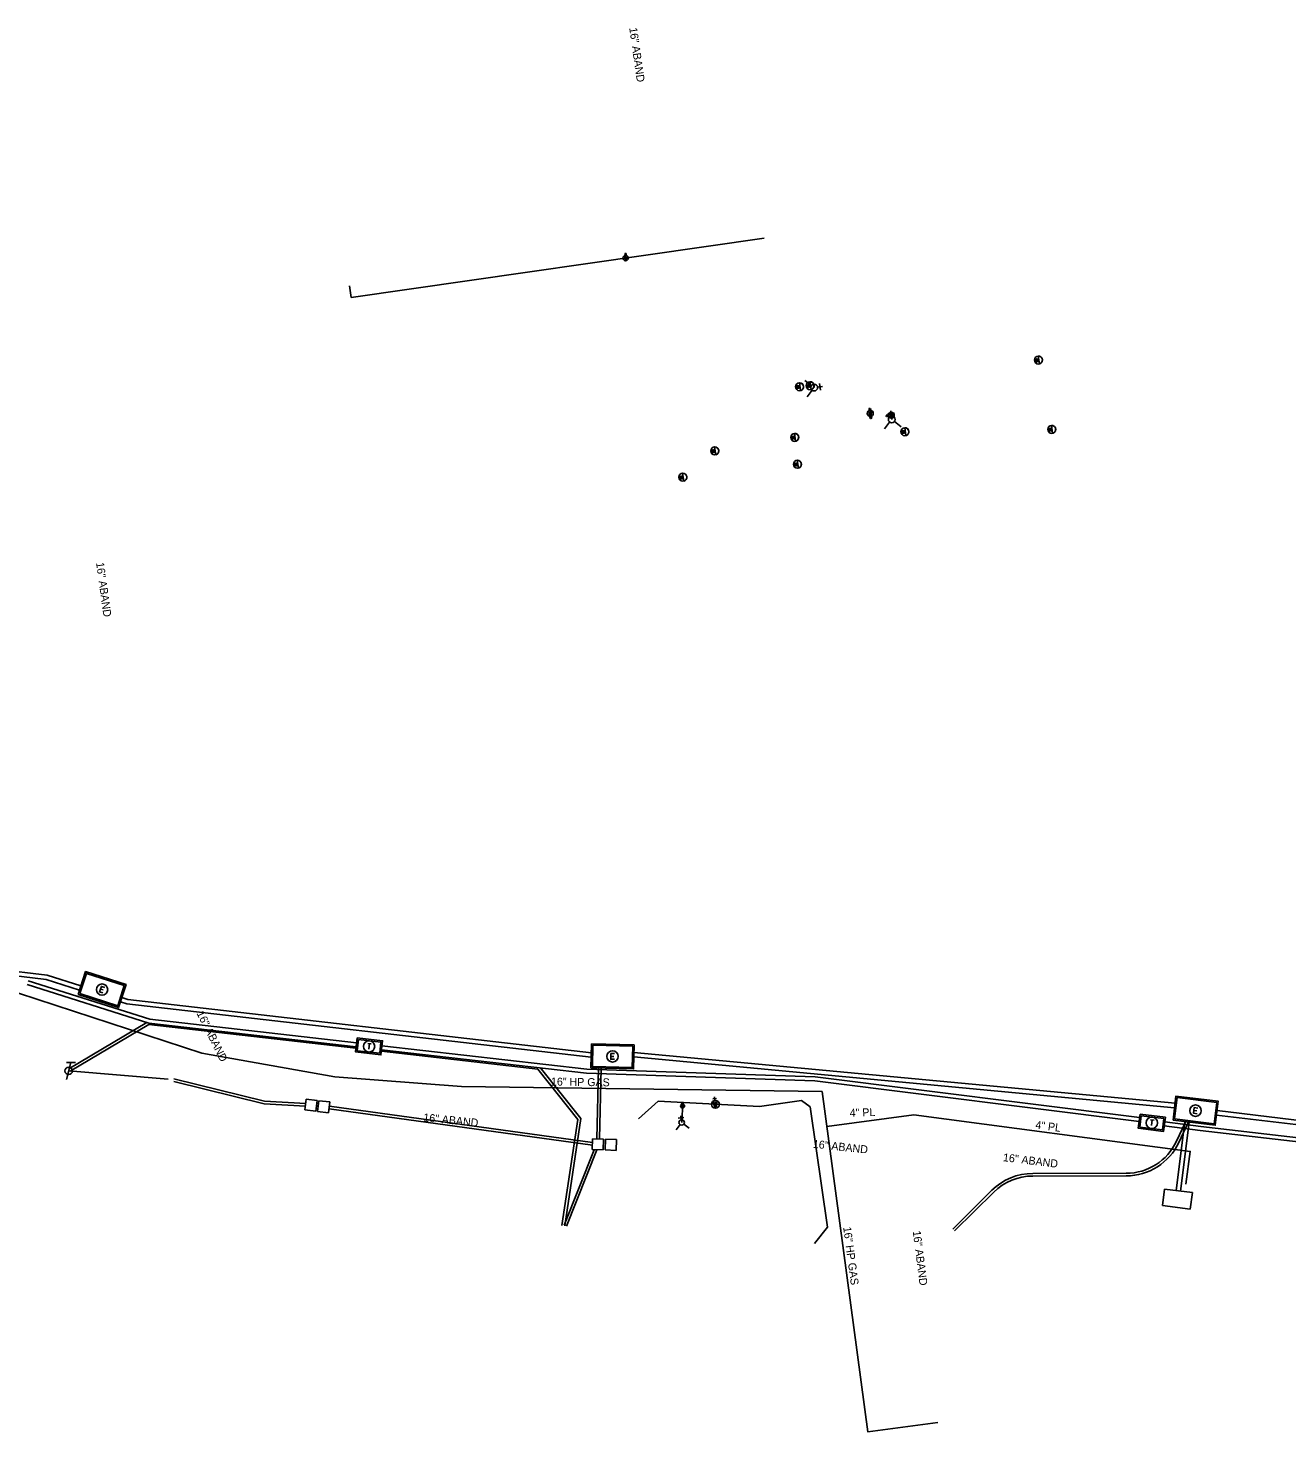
# Model space of a CAD drawing. Extents: x 1825330 to 1832613, y 710925 to 712586.
# Drawn here: x 1827870.9 to 1828314.3, y 711497 to 711991.4 of the extents above; entities that cross this region are included whole.
import ezdxf

# ---------------------------------------------------------------- set-up
doc = ezdxf.new("R2010")
doc.units = 0
for name, color, linetype in [('COC_BLD', 7, 'Continuous'), ('COC_UELC_GUY', 7, 'Continuous'), ('COC_USAN_MH', 7, 'Continuous'), ('COC_USAN_MH_TEXT', 7, 'Continuous'), ('COC_UWAT_HYD', 7, 'Continuous'), ('P-TEXT', 7, 'Continuous'), ('STDSHT', 7, 'Continuous'), ('ZM-BORDERS', 7, 'Continuous')]:
    doc.layers.add(name, color=color, linetype=linetype)

msp = doc.modelspace()

# ---------------------------------------------------------------- linework, layer by layer
msp.add_lwpolyline([(1828262.52, 711608.89), (1828271.45, 711607.78), (1828270.83, 711602.81), (1828261.9, 711603.93)], close=True)
at = {"layer": 'COC_UELC_GUY'}
for p, q in [((1827984.65, 711896.54), (1828130.11, 711917.41)), ((1827984.06, 711900.61), (1827984.65, 711896.54)), ((1828175.08, 711853.55), (1828174.73, 711856.54)), ((1828085.9, 711607.25), (1828092.77, 711613.44)), ((1828092.77, 711613.44), (1828128.48, 711611.57)), ((1828101.1, 711605.99), (1828101.46, 711612.98)), ((1828128.48, 711611.57), (1828143.32, 711613.73)), ((1828146.36, 711611.46), (1828143.32, 711613.73))]:
    msp.add_line(p, q, dxfattribs=at)
msp.add_lwpolyline([(1828147.91, 711563.32), (1828152.51, 711569.04), (1828146.36, 711611.46)], dxfattribs=at)
at = {"layer": 'COC_USAN_MH'}
msp.add_line((1828023.5, 711618.65), (1828150.6, 711616.84), dxfattribs=at)
for points in [[(1827861.07, 711653.59), (1827932.11, 711630.33), (1827978.94, 711622.09), (1828023.5, 711618.65)], [(1828150.6, 711616.84), (1828166.68, 711496.98), (1828191.27, 711500.35)], [(1828152.25, 711604.52), (1828182.89, 711608.64), (1828280.19, 711595.75), (1828278.63, 711584.24)]]:
    msp.add_lwpolyline(points, dxfattribs=at)
at = {"layer": 'COC_USAN_MH_TEXT'}
for p, q in [((1827870.9, 711655.89), (1827913.78, 711642.33)), ((1827870.6, 711654.5), (1827913.48, 711640.94)), ((1827885.24, 711624.88), (1827912.71, 711641.18)), ((1827913.78, 711642.33), (1827986.6, 711633.99)), ((1827885.75, 711624.02), (1827913.43, 711640.44)), ((1827913.43, 711640.44), (1827986.38, 711632.08)), ((1827913.48, 711640.94), (1827986.44, 711632.58)), ((1827991.78, 711633.65), (1827990.54, 711633.8)), ((1827991.12, 711633.73), (1827990.87, 711631.74)), ((1827995.38, 711631.55), (1828067.61, 711623.28)), ((1827995.54, 711632.96), (1828067.71, 711624.69)), ((1827995.32, 711631.06), (1828050.46, 711624.74)), ((1828050.46, 711624.74), (1828064.54, 711607.02)), ((1828051.25, 711625.36), (1828065.58, 711607.32)), ((1828067.61, 711623.28), (1828148, 711620.63)), ((1828067.71, 711624.69), (1828148.11, 711622.05)), ((1828148.11, 711622.05), (1828262.38, 711607.77)), ((1828148, 711620.63), (1828262.2, 711606.36)), ((1828058.92, 711569.63), (1828064.54, 711607.02)), ((1828059.9, 711569.52), (1828065.58, 711607.32)), ((1828267.46, 711606.77), (1828266.22, 711606.92)), ((1828266.8, 711606.86), (1828266.55, 711604.87)), ((1828271.07, 711604.75), (1828283.72, 711603.17)), ((1828271.25, 711606.16), (1828283.9, 711604.57)), ((1828283.73, 711603.17), (1828515.03, 711576.14)), ((1828283.9, 711604.57), (1828515.2, 711577.54))]:
    msp.add_line(p, q, dxfattribs=at)
for points in [[(1827986.8, 711635.76), (1827995.75, 711634.74), (1827995.18, 711629.77), (1827986.23, 711630.8)], [(1827987.24, 711635.21), (1827995.19, 711634.3), (1827994.74, 711630.33), (1827986.79, 711631.24)], [(1828262.95, 711608.33), (1828270.89, 711607.34), (1828270.39, 711603.37), (1828262.46, 711604.36)]]:
    msp.add_lwpolyline(points, close=True, dxfattribs=at)
for centre in [(1827990.99, 711632.77), (1828266.67, 711605.85)]:
    msp.add_circle(centre, 2, dxfattribs=at)
at = {"layer": 'COC_UWAT_HYD'}
for p, q in [((1827706.52, 711678.86), (1827877.6, 711657.83)), ((1827706.54, 711677.26), (1827877.26, 711656.28)), ((1827877.26, 711656.28), (1827889.03, 711652.56)), ((1827877.6, 711657.83), (1827889.5, 711654.07)), ((1827896.41, 711652.96), (1827897.36, 711652.65)), ((1827903.44, 711648.41), (1827905.73, 711647.69)), ((1827903.92, 711649.92), (1827906.06, 711649.24)), ((1827905.73, 711647.69), (1828069.24, 711628.94)), ((1827906.06, 711649.24), (1828069.28, 711630.53)), ((1828076.17, 711629.25), (1828077.17, 711629.23)), ((1828084.2, 711629.05), (1828274.71, 711611.17)), ((1828084.29, 711630.63), (1828274.88, 711612.75)), ((1827885.2, 711624.12), (1827920.28, 711621.24)), ((1828071.78, 711625.09), (1828071.19, 711600.18)), ((1828072.7, 711625.07), (1828072.11, 711600.16)), ((1827968.39, 711610.38), (1827968.85, 711614.18)), ((1827968.85, 711614.18), (1827972.66, 711613.72)), ((1827972.66, 711613.72), (1827972.2, 711609.92)), ((1827972.88, 711609.83), (1827973.34, 711613.64)), ((1827973.34, 711613.64), (1827977.14, 711613.18)), ((1827977.14, 711613.18), (1827976.68, 711609.37)), ((1827977.02, 711611.73), (1828069.65, 711598.91)), ((1827972.2, 711609.92), (1827968.39, 711610.38)), ((1827976.68, 711609.37), (1827972.88, 711609.83)), ((1827976.91, 711610.8), (1828069.7, 711597.95)), ((1828281.49, 711610.21), (1828282.48, 711610.08)), ((1828289.47, 711608.57), (1828500.81, 711583.36)), ((1828289.66, 711610.14), (1828501, 711584.94)), ((1828278.32, 711606.31), (1828275.28, 711582)), ((1828275.35, 711599.33), (1828278.6, 711606.27)), ((1828276.18, 711598.94), (1828279.56, 711606.15)), ((1828279.8, 711606.12), (1828276.76, 711581.81)), ((1828069.61, 711596.4), (1828069.73, 711600.23)), ((1828069.73, 711600.23), (1828073.56, 711600.11)), ((1828073.56, 711600.11), (1828073.44, 711596.28)), ((1828074.14, 711596.27), (1828074.27, 711600.1)), ((1828074.27, 711600.1), (1828078.1, 711599.97)), ((1828078.1, 711599.97), (1828077.97, 711596.14)), ((1828070.23, 711596.38), (1828059.69, 711569.76)), ((1828071.21, 711596.35), (1828060.55, 711569.42)), ((1828073.44, 711596.28), (1828069.61, 711596.4)), ((1828077.97, 711596.14), (1828074.14, 711596.27)), ((1828224.75, 711588.03), (1828257.67, 711588.07)), ((1828224.75, 711587.11), (1828257.67, 711587.15)), ((1828196.58, 711568.42), (1828210.36, 711582.1)), ((1828270.43, 711576.74), (1828271.18, 711582.53)), ((1828271.18, 711582.53), (1828280.98, 711581.26)), ((1828197.23, 711567.77), (1828211.01, 711581.44)), ((1828280.98, 711581.26), (1828280.23, 711575.47)), ((1828280.23, 711575.47), (1828270.43, 711576.74))]:
    msp.add_line(p, q, dxfattribs=at)
for points in [[(1827888.52, 711651.02), (1827891.13, 711659.11), (1827905.41, 711654.52), (1827902.8, 711646.42)], [(1827889.15, 711651.34), (1827891.45, 711658.48), (1827904.78, 711654.19), (1827902.48, 711647.05)], [(1828069.15, 711625.16), (1828069.36, 711633.65), (1828084.35, 711633.3), (1828084.15, 711624.8)], [(1828069.84, 711633.14), (1828083.84, 711632.81), (1828083.66, 711625.31), (1828069.66, 711625.64)], [(1828274.14, 711606.83), (1828275.19, 711615.27), (1828290.08, 711613.41), (1828289.02, 711604.97)], [(1828275.63, 711614.71), (1828289.52, 711612.97), (1828288.59, 711605.53), (1828274.7, 711607.27)]]:
    msp.add_lwpolyline(points, close=True, dxfattribs=at)
for points in [[(1827897.91, 711653.53), (1827896.72, 711653.91), (1827896.1, 711652), (1827897.29, 711651.62)], [(1828077.44, 711630.22), (1828076.19, 711630.25), (1828076.14, 711628.25), (1828077.39, 711628.22)], [(1827922.26, 711621.35), (1827954.21, 711613.47), (1827968.74, 711612.69)], [(1827922.24, 711620.43), (1827954, 711612.56), (1827968.62, 711611.73)], [(1828282.86, 711611.04), (1828281.61, 711611.2), (1828281.37, 711609.21), (1828282.61, 711609.06)]]:
    msp.add_lwpolyline(points, dxfattribs=at)
for centre in [(1827896.96, 711652.77), (1828076.75, 711629.23), (1828282.07, 711610.12)]:
    msp.add_circle(centre, 2, dxfattribs=at)
for centre, radius, start, end in [((1828257.65, 711607.61), 19.54, 270.0553, 334.9333), ((1828257.65, 711607.61), 20.46, 270.0553, 334.9333), ((1828224.77, 711567.57), 20.46, 90.0553, 134.7815), ((1828224.77, 711567.57), 19.54, 90.0553, 134.7815)]:
    msp.add_arc(centre, radius, start, end, dxfattribs=at)
at = {"layer": 'P-TEXT'}
for p, q in [((1828081.79, 711911.8), (1828080.92, 711911.8)), ((1828081.35, 711911.37), (1828081.35, 711912.23)), ((1828227.09, 711873.12), (1828226.69, 711875.87)), ((1828142.94, 711863.71), (1828142.54, 711866.47)), ((1828146.82, 711865.51), (1828144.47, 711867.28)), ((1828147.06, 711863.84), (1828145.3, 711861.48)), ((1828146.65, 711864.08), (1828146.25, 711866.84)), ((1828148.97, 711864.97), (1828150.67, 711865.21)), ((1828149.99, 711863.9), (1828149.65, 711866.28)), ((1828167.79, 711857.29), (1828166.84, 711857.15)), ((1828167.38, 711856.75), (1828167.25, 711857.69)), ((1828167.32, 711854.24), (1828168.08, 711854.33)), ((1828167.66, 711854.67), (1828167.75, 711853.9)), ((1828173.87, 711854.89), (1828172.93, 711854.74)), ((1828173.32, 711855.29), (1828173.47, 711854.34)), ((1828176.02, 711855.74), (1828173.64, 711855.45)), ((1828174.93, 711854.74), (1828174.72, 711856.45)), ((1828174.34, 711852.6), (1828172.53, 711850.29)), ((1828176.02, 711852.81), (1828178.34, 711851)), ((1828180.03, 711847.87), (1828179.64, 711850.63)), ((1828231.75, 711848.71), (1828231.36, 711851.46)), ((1828113.08, 711841.11), (1828112.68, 711843.87)), ((1828141.24, 711845.89), (1828140.84, 711848.65)), ((1828142.19, 711836.43), (1828141.79, 711839.19)), ((1828101.83, 711831.87), (1828101.43, 711834.62)), ((1828101.57, 711612.86), (1828100.93, 711612.76)), ((1828101.3, 711612.49), (1828101.2, 711613.13)), ((1828113.35, 711614.45), (1828112.09, 711614.29)), ((1828112.8, 711613.74), (1828112.64, 711615)), ((1828101.81, 711607.76), (1828099.91, 711607.49)), ((1828100.96, 711606.94), (1828100.76, 711608.31)), ((1828100.53, 711605.22), (1828099.12, 711603.34)), ((1828101.87, 711605.42), (1828103.75, 711604.01))]:
    msp.add_line(p, q, dxfattribs=at)
for points in [[(1828080.92, 711910.96), (1828081.14, 711909.79), (1828081.35, 711910.96), (1828081.57, 711909.79), (1828081.79, 711910.96)], [(1828225.71, 711874.89), (1828226.07, 711873.81), (1828226.12, 711874.95), (1828226.48, 711873.87), (1828226.53, 711875.01)], [(1828141.56, 711865.49), (1828141.92, 711864.41), (1828141.97, 711865.55), (1828142.33, 711864.47), (1828142.38, 711865.61)], [(1828145.27, 711865.86), (1828145.64, 711864.78), (1828145.68, 711865.92), (1828146.05, 711864.84), (1828146.09, 711865.98)], [(1828166.97, 711856.24), (1828167.4, 711854.99), (1828167.45, 711856.31), (1828167.87, 711855.06), (1828167.92, 711856.38)], [(1828174.38, 711854.48), (1828175.62, 711854.91), (1828174.31, 711854.95), (1828175.55, 711855.39), (1828174.24, 711855.43)], [(1828178.65, 711849.64), (1828179.02, 711848.56), (1828179.06, 711849.7), (1828179.43, 711848.62), (1828179.47, 711849.76)], [(1828230.37, 711850.48), (1828230.74, 711849.4), (1828230.78, 711850.54), (1828231.15, 711849.46), (1828231.19, 711850.6)], [(1828139.86, 711847.67), (1828140.22, 711846.59), (1828140.27, 711847.73), (1828140.63, 711846.65), (1828140.68, 711847.79)], [(1828111.69, 711842.89), (1828112.06, 711841.81), (1828112.1, 711842.95), (1828112.47, 711841.87), (1828112.51, 711843)], [(1828140.81, 711838.21), (1828141.17, 711837.13), (1828141.22, 711838.27), (1828141.58, 711837.19), (1828141.63, 711838.33)], [(1828100.45, 711833.64), (1828100.81, 711832.56), (1828100.86, 711833.7), (1828101.22, 711832.62), (1828101.27, 711833.76)], [(1828101.02, 711612.14), (1828101.31, 711611.29), (1828101.34, 711612.18), (1828101.63, 711611.34), (1828101.66, 711612.23)], [(1828112.24, 711613.07), (1828112.77, 711611.4), (1828112.87, 711613.15), (1828113.4, 711611.48), (1828113.51, 711613.23)]]:
    msp.add_lwpolyline(points, dxfattribs=at)
for centre, radius in [((1828081.35, 711910.42), 0.952), ((1828226.75, 711874.47), 1.4), ((1828142.6, 711865.07), 1.4), ((1828146.31, 711865.44), 1.4), ((1828147.78, 711864.8), 1.2), ((1828167.53, 711855.71), 1.05), ((1828167.7, 711854.28), 0.386), ((1828174.91, 711855.05), 1.05), ((1828175.08, 711853.55), 1.2), ((1828179.7, 711849.23), 1.4), ((1828231.42, 711850.06), 1.4), ((1828112.74, 711842.47), 1.4), ((1828140.9, 711847.25), 1.4), ((1828141.85, 711837.79), 1.4), ((1828101.49, 711833.23), 1.4), ((1828101.4, 711611.78), 0.717), ((1828112.97, 711612.35), 1.4), ((1828101.1, 711605.99), 0.96)]:
    msp.add_circle(centre, radius, dxfattribs=at)
for centre in [(1828226.75, 711874.47), (1828226.75, 711874.47), (1828142.6, 711865.07), (1828142.6, 711865.07), (1828146.31, 711865.44), (1828146.31, 711865.44), (1828179.7, 711849.23), (1828179.7, 711849.23), (1828231.42, 711850.06), (1828231.42, 711850.06), (1828112.74, 711842.47), (1828112.74, 711842.47), (1828140.9, 711847.25), (1828140.9, 711847.25), (1828141.85, 711837.79), (1828141.85, 711837.79), (1828101.49, 711833.23), (1828101.49, 711833.23)]:
    msp.add_arc(centre, 1.4, 283.9445, 92.4652, dxfattribs=at)
at = {"layer": 'STDSHT'}
for p, q in [((1827886, 711627.12), (1827884.39, 711621.12)), ((1827887.6, 711627.12), (1827884.4, 711627.12))]:
    msp.add_line(p, q, dxfattribs=at)
msp.add_circle((1827885.2, 711624.12), 1.3, dxfattribs=at)
at = {"layer": 'ZM-BORDERS'}
msp.add_line((1828147.64, 711865.79), (1828147.78, 711864.8), dxfattribs=at)

# ---------------------------------------------------------------- texts
at = {"layer": 'COC_BLD'}
for s, rotation, p in [('16" ABAND', 278.1514, (1828082.61, 711991.43)), ('16" ABAND', 277.8948, (1827894.85, 711803.09)), ('16" ABAND', 296.3017, (1827930.16, 711644.45)), ('16" HP GAS', 359.1807, (1828055.05, 711618.98)), ('16" ABAND', 354.0561, (1828010, 711606.43)), ('4" PL', 1.9522, (1828160.31, 711607.94)), ('4" PL', 352.467, (1828225.53, 711603.83)), ('16" ABAND', 353.8253, (1828147.2, 711597.09)), ('16" ABAND', 352.9939, (1828214.15, 711592.36)), ('16" HP GAS', 277.6433, (1828157.96, 711569.05)), ('16" ABAND', 277.2774, (1828182.47, 711567.66))]:
    msp.add_text(s, height=2.8, rotation=rotation, dxfattribs=at).set_placement(p)

doc.saveas('drawing.dxf')
